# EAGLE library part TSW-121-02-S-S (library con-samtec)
THROUGH-HOLE .025" SQ POST HEADER Source: Samtec TSW.pdf
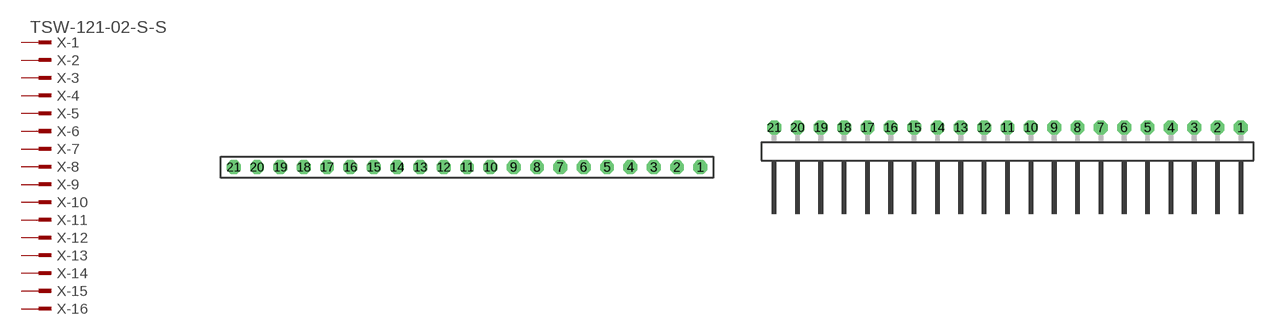
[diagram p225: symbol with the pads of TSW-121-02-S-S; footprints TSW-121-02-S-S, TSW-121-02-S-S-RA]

Designator prefix X; gates -1=MPINV -2=MPIN -3=MPIN -4=MPIN -5=MPIN -6=MPIN -7=MPIN -8=MPIN -9=MPIN -10=MPIN -11=MPIN -12=MPIN -13=MPIN -14=MPIN -15=MPIN -16=MPIN -17=MPIN -18=MPIN -19=MPIN -20=MPIN -21=MPIN

## TSW-121-02-S-S (OC_FARNELL: unknown; OC_NEWARK: unknown)  [TSW-121-02-S-S]
1  -1:1  pas
2  -2:1  pas
3  -3:1  pas
4  -4:1  pas
5  -5:1  pas
6  -6:1  pas
7  -7:1  pas
8  -8:1  pas
9  -9:1  pas
10  -10:1  pas
11  -11:1  pas
12  -12:1  pas
13  -13:1  pas
14  -14:1  pas
15  -15:1  pas
16  -16:1  pas
17  -17:1  pas
18  -18:1  pas
19  -19:1  pas
20  -20:1  pas
21  -21:1  pas

## TSW-121-02-S-S-RA (OC_FARNELL: unknown; OC_NEWARK: unknown)  [TSW-121-02-S-S-RA]
Pads as for TSW-121-02-S-S

## Footprint TSW-121-02-S-S (pad centres in mm)
THROUGH-HOLE .025" SQ POST HEADER Source: Samtec TSW.pdf
drill 1 pad 1.5 octagon: 1 25.4,0; 2 22.86,0; 3 20.32,0; 4 17.78,0; 5 15.24,0; 6 12.7,0; 7 10.16,0; 8 7.62,0; 9 5.08,0; 10 2.54,0; 11 0,0; 12 -2.54,0; 13 -5.08,0; 14 -7.62,0; 15 -10.16,0; 16 -12.7,0; 17 -15.24,0; 18 -17.78,0; 19 -20.32,0; 20 -22.86,0; 21 -25.4,0

## Footprint TSW-121-02-S-S-RA (pad centres in mm)
THROUGH-HOLE .025" SQ POST HEADER Source: Samtec TSW.pdf
drill 1 pad 1.5 octagon: 1 25.4,1.524; 2 22.86,1.524; 3 20.32,1.524; 4 17.78,1.524; 5 15.24,1.524; 6 12.7,1.524; 7 10.16,1.524; 8 7.62,1.524; 9 5.08,1.524; 10 2.54,1.524; 11 0,1.524; 12 -2.54,1.524; 13 -5.08,1.524; 14 -7.62,1.524; 15 -10.16,1.524; 16 -12.7,1.524; 17 -15.24,1.524; 18 -17.78,1.524; 19 -20.32,1.524; 20 -22.86,1.524; 21 -25.4,1.524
